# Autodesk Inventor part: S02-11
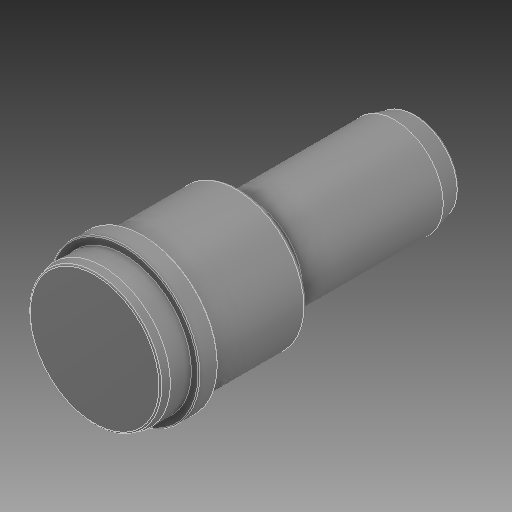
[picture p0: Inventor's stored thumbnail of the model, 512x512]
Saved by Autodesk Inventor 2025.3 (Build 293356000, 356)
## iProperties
Created: 2025-04
Part Number: S02-11
Material: Všeobecné
Document SubType Name: Modeling
Designer: Patrik
Density: 1 g/cm^3
Appearance: Výchozí
Stock Number: E 1002 DLC/30-36/55
Description: Vodící kolík s nákružkem
User Status: 1.7131
Mass: 102.383 g
Surface Area: 141.175 cm^2
Volume: 102.383 cm^3
Author: Patrik
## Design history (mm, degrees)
feature "Base1"
node "Těleso1"
